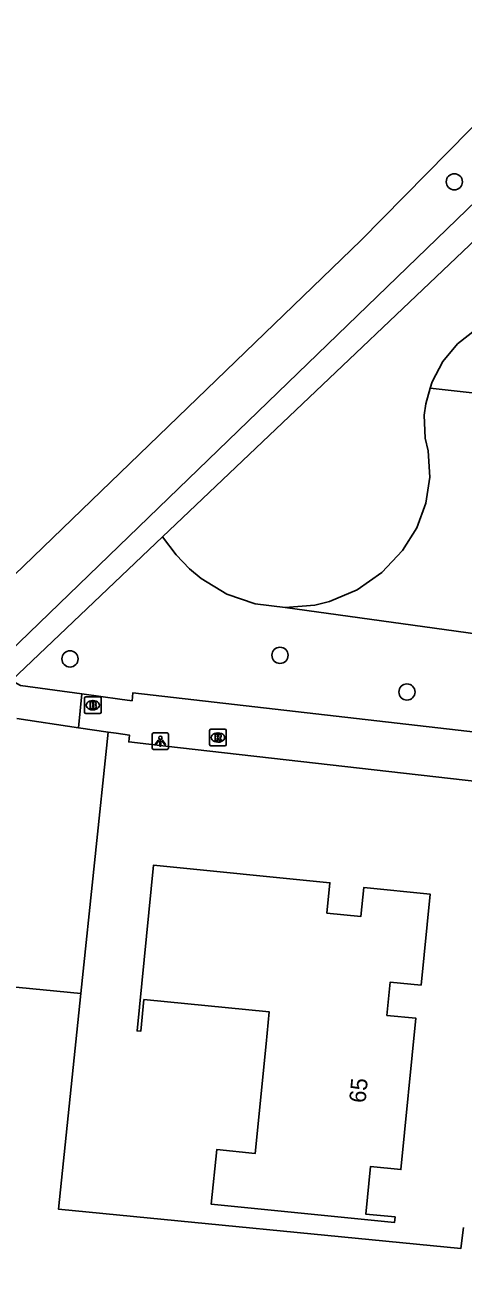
# Model space of a CAD drawing. Extents: x 162398 to 163643, y 386453 to 387397.
# Drawn here: x 162925.6 to 162952, y 387103.2 to 387178.6 of the extents above; entities that cross this region are included whole.
import ezdxf

# ---------------------------------------------------------------- set-up
doc = ezdxf.new("R2010")
doc.units = 0
for name, color, linetype in [('IMGEO_Boom', 7, 'Continuous'), ('IMGEO_Brandkraan', 7, 'Continuous'), ('IMGEO_Groenvoorziening', 7, 'Continuous'), ('IMGEO_Lichtpunt', 7, 'Continuous'), ('IMGEO_Meer_plas_ven_vijver', 7, 'Continuous'), ('IMGEO_Pand', 7, 'Continuous'), ('IMGEO_Pand_nummerreeks', 7, 'Continuous'), ('IMGEO_Rioolput', 7, 'Continuous'), ('IMGEO_Voetpad_halfverhard', 7, 'Continuous'), ('IMGEO_Voetpad_open', 7, 'Continuous')]:
    doc.layers.add(name, color=color, linetype=linetype)

msp = doc.modelspace()

# ---------------------------------------------------------------- linework, layer by layer
at = {"layer": 'IMGEO_Boom'}
for centre in [(162951.492, 387169.124), (162928.28, 387140.296), (162940.961, 387140.515), (162948.63, 387138.296)]:
    msp.add_circle(centre, 0.489, dxfattribs=at)
at = {"layer": 'IMGEO_Brandkraan'}
for p, q in [((162929.155, 387137.072), (162929.155, 387137.924)), ((162929.23, 387137.998), (162930.082, 387137.998)), ((162929.643, 387137.778), (162929.668, 387137.778)), ((162930.156, 387137.924), (162930.156, 387137.072)), ((162930.082, 387136.998), (162929.23, 387136.998)), ((162929.666, 387137.218), (162929.641, 387137.218))]:
    msp.add_line(p, q, dxfattribs=at)
for points in [[(162929.155, 387137.072), (162929.155, 387137.924)], [(162929.23, 387137.998), (162930.082, 387137.998)], [(162929.503, 387137.698), (162929.503, 387137.298), (162929.716, 387137.298)], [(162929.734, 387137.698), (162929.503, 387137.698)], [(162929.682, 387137.617), (162929.628, 387137.617), (162929.628, 387137.541)], [(162929.628, 387137.541), (162929.681, 387137.541)], [(162929.69, 387137.465), (162929.628, 387137.465), (162929.628, 387137.384)], [(162929.628, 387137.384), (162929.69, 387137.384)], [(162930.156, 387137.924), (162930.156, 387137.072)], [(162930.082, 387136.998), (162929.23, 387136.998)]]:
    msp.add_lwpolyline(points, dxfattribs=at)
for centre, radius, start, end in [((162929.232, 387137.922), 0.0765, 91.55205, 178.44795), ((162929.232, 387137.922), 0.0765, 91.55205, 178.44795), ((162929.683, 387137.579), 0.0379, 267.82845, 90.93552), ((162929.691, 387137.424), 0.0404, 269.87594, 90.50774), ((162929.738, 387137.553), 0.145, 59.4692, 91.53667), ((162929.763, 387137.6), 0.0922, 285.51372, 58.15012), ((162929.768, 387137.408), 0.105, 301.31148, 78.98903), ((162930.08, 387137.922), 0.0765, 1.55205, 88.44795), ((162930.08, 387137.922), 0.0765, 1.55205, 88.44795), ((162929.232, 387137.074), 0.0765, 181.55205, 268.44795), ((162929.232, 387137.074), 0.0765, 181.55205, 268.44795), ((162929.722, 387137.549), 0.251, 268.66757, 293.53466), ((162930.08, 387137.074), 0.0765, 271.55205, 358.44795), ((162930.08, 387137.074), 0.0765, 271.55205, 358.44795)]:
    msp.add_arc(centre, radius, start, end, dxfattribs=at)
for centre, major_axis, ratio, start_param, end_param in [((162929.642, 387137.498), (-0.387, 0.002), 0.722429, 4.712389, 7.853982), ((162929.667, 387137.498), (-0.39, 0.002), 0.717154, 1.570796, 4.712389)]:
    msp.add_ellipse(centre, major_axis=major_axis, ratio=ratio, start_param=start_param, end_param=end_param, dxfattribs=at)
at = {"layer": 'IMGEO_Groenvoorziening'}
for points in [[(162950.035, 387156.654), (162950.146, 387157.044), (162950.798, 387158.272), (162951.69, 387159.338), (162952.785, 387160.195), (162954.034, 387160.805), (162955.383, 387161.143), (162956.772, 387161.193), (162971.313, 387159.479), (162974.954, 387164.968), (162979.098, 387161.653), (162978.659, 387160.475)], [(162950.035, 387156.654), (162949.764, 387155.707), (162949.68, 387155.016), (162949.728, 387153.642), (162949.903, 387152.865), (162950.005, 387151.279), (162949.775, 387149.705), (162949.223, 387148.214), (162948.352, 387146.844), (162947.113, 387145.518), (162945.626, 387144.478), (162943.955, 387143.771), (162943.074, 387143.552), (162941.266, 387143.395)], [(162956.38, 387155.957), (162950.035, 387156.654)], [(162941.266, 387143.395), (162939.465, 387143.617), (162937.75, 387144.21), (162936.195, 387145.145), (162935.5, 387145.73), (162934.7, 387146.585), (162933.874, 387147.675)], [(162941.266, 387143.395), (162954.796, 387141.535)], [(162930.576, 387135.875), (162928.93, 387120.073)], [(162924.374, 387120.523), (162928.93, 387120.073)], [(162928.93, 387120.073), (162927.574, 387107.059), (162951.889, 387104.679), (162952.055, 387105.95)]]:
    msp.add_lwpolyline(points, dxfattribs=at)
at = {"layer": 'IMGEO_Lichtpunt'}
for p, q in [((162933.238, 387135.73), (162933.238, 387134.923)), ((162933.238, 387135.73), (162933.238, 387134.923)), ((162934.14, 387135.825), (162933.332, 387135.825)), ((162934.14, 387135.825), (162933.332, 387135.825)), ((162934.234, 387134.923), (162934.234, 387135.73)), ((162934.234, 387134.923), (162934.234, 387135.73)), ((162933.332, 387134.829), (162934.14, 387134.829)), ((162933.332, 387134.829), (162934.14, 387134.829))]:
    msp.add_line(p, q, dxfattribs=at)
for points in [[(162933.612, 387135.394), (162933.651, 387135.366), (162933.463, 387135.104), (162933.425, 387135.131), (162933.612, 387135.394)], [(162933.714, 387135.346), (162933.761, 387135.346), (162933.761, 387135.024), (162933.714, 387135.024), (162933.714, 387135.346)], [(162933.824, 387135.366), (162933.862, 387135.393), (162934.049, 387135.131), (162934.01, 387135.103), (162933.824, 387135.366)]]:
    msp.add_lwpolyline(points, dxfattribs=at)
msp.add_circle((162933.737, 387135.528), 0.0994, dxfattribs=at)
for centre, start, end in [((162933.332, 387135.73), 90, 180), ((162933.332, 387135.73), 90, 180), ((162934.14, 387135.73), 0, 90), ((162934.14, 387135.73), 0, 90), ((162933.332, 387134.923), 180, 270), ((162933.332, 387134.923), 180, 270), ((162934.14, 387134.923), 270, 0), ((162934.14, 387134.923), 270, 360)]:
    msp.add_arc(centre, 0.0946, start, end, dxfattribs=at)
at = {"layer": 'IMGEO_Meer_plas_ven_vijver'}
msp.add_lwpolyline([(162846.89, 387045.895), (162849.85, 387050.53), (162865.986, 387076.424), (162874.5, 387090.087), (162877.58, 387095.446), (162881.241, 387100.793), (162883.801, 387104.202), (162884.941, 387105.402), (162887.051, 387108.121), (162890.58, 387112.23), (162945.852, 387165.587), (162955.059, 387174.946), (162962.124, 387182.486), (162969.073, 387188.983), (162970.442, 387190.315)], dxfattribs=at)
at = {"layer": 'IMGEO_Pand'}
msp.add_lwpolyline([(162932.745, 387119.72), (162940.318, 387118.97), (162940.128, 387117.047), (162939.471, 387110.417), (162937.141, 387110.648), (162936.814, 387107.347), (162947.881, 387106.251), (162947.914, 387106.579), (162946.139, 387106.755), (162946.423, 387109.621), (162948.263, 387109.439), (162949.169, 387118.585), (162947.419, 387118.758), (162947.618, 387120.774), (162949.482, 387120.59), (162950.026, 387126.084), (162946.024, 387126.48), (162945.852, 387124.739), (162943.801, 387124.942), (162943.982, 387126.767), (162933.317, 387127.824), (162932.326, 387117.819), (162932.555, 387117.797), (162932.745, 387119.72)], dxfattribs=at)
at = {"layer": 'IMGEO_Rioolput'}
for p, q in [((162936.713, 387135.12), (162936.713, 387135.972)), ((162936.788, 387136.046), (162937.64, 387136.046)), ((162937.714, 387135.972), (162937.714, 387135.12)), ((162937.224, 387135.266), (162937.199, 387135.266)), ((162937.201, 387135.826), (162937.226, 387135.826)), ((162937.64, 387135.046), (162936.788, 387135.046))]:
    msp.add_line(p, q, dxfattribs=at)
for points in [[(162936.713, 387135.12), (162936.713, 387135.972)], [(162936.788, 387136.046), (162937.64, 387136.046)], [(162937.714, 387135.972), (162937.714, 387135.12)], [(162937.302, 387135.744), (162937.05, 387135.746), (162937.05, 387135.346)], [(162937.05, 387135.346), (162937.174, 387135.346), (162937.174, 387135.508), (162937.185, 387135.508)], [(162937.228, 387135.665), (162937.174, 387135.665), (162937.174, 387135.584)], [(162937.174, 387135.584), (162937.226, 387135.584)], [(162937.232, 387135.479), (162937.303, 387135.346), (162937.443, 387135.346), (162937.378, 387135.472)], [(162937.64, 387135.046), (162936.788, 387135.046)]]:
    msp.add_lwpolyline(points, dxfattribs=at)
for centre, radius, start, end in [((162936.79, 387135.97), 0.0765, 91.55205, 178.44795), ((162936.79, 387135.97), 0.0765, 91.55205, 178.44795), ((162937.638, 387135.97), 0.0765, 1.55205, 88.44795), ((162937.638, 387135.97), 0.0765, 1.55205, 88.44795), ((162936.79, 387135.122), 0.0765, 181.55205, 268.44795), ((162936.79, 387135.122), 0.0765, 181.55205, 268.44795), ((162937.184, 387135.455), 0.0533, 26.02933, 88.69889), ((162937.21, 387135.773), 0.19, 274.7715, 282.96867), ((162937.234, 387135.569), 0.0964, 77.00612, 93.18647), ((162937.248, 387135.626), 0.0378, 276.66336, 79.67722), ((162937.301, 387135.634), 0.109, 350.36119, 89.41601), ((162937.299, 387135.634), 0.112, 277.58423, 350.98172), ((162937.283, 387135.419), 0.108, 29.51342, 73.79051), ((162937.638, 387135.122), 0.0765, 271.55205, 358.44795), ((162937.638, 387135.122), 0.0765, 271.55205, 358.44795)]:
    msp.add_arc(centre, radius, start, end, dxfattribs=at)
for centre, major_axis, ratio, start_param, end_param in [((162937.2, 387135.546), (-0.387, 0.002), 0.722429, 4.712389, 7.853982), ((162937.225, 387135.546), (-0.39, 0.002), 0.717154, 1.570796, 4.712389)]:
    msp.add_ellipse(centre, major_axis=major_axis, ratio=ratio, start_param=start_param, end_param=end_param, dxfattribs=at)
at = {"layer": 'IMGEO_Voetpad_halfverhard'}
for points in [[(162990.622, 387191.429), (162988.981, 387190.548), (162986.564, 387190.198), (162981.995, 387189.888), (162978.312, 387189.488), (162977.07, 387188.884), (162972.048, 387185.44), (162966.778, 387181.153), (162958.243, 387173.224), (162916.196, 387132.579), (162904.234, 387119.646), (162889.742, 387105.631), (162883.217, 387098.659), (162878.712, 387092.096), (162876.773, 387088.486), (162875.505, 387085.945), (162852.417, 387048.899), (162851.569, 387047.532), (162851.368, 387046.853), (162851.155, 387042.928)], [(162991.45, 387188.438), (162989.743, 387188.941), (162980.431, 387188.074), (162977.398, 387187.341), (162973.446, 387184.5), (162967.441, 387179.498), (162959.252, 387171.801), (162933.874, 387147.675)], [(162933.874, 387147.675), (162924.751, 387138.998), (162925.28, 387138.681)]]:
    msp.add_lwpolyline(points, dxfattribs=at)
at = {"layer": 'IMGEO_Voetpad_open'}
for points in [[(162925.28, 387138.681), (162928.991, 387138.18)], [(162928.991, 387138.18), (162928.798, 387136.138)], [(162928.991, 387138.18), (162931.284, 387137.871), (162932.025, 387137.771), (162932.076, 387138.251), (162954.173, 387135.713)], [(162928.798, 387136.138), (162925.06, 387136.69)], [(162928.798, 387136.138), (162930.576, 387135.875)], [(162930.576, 387135.875), (162931.077, 387135.801), (162931.881, 387135.682), (162931.83, 387135.282), (162934.076, 387135.027), (162954.814, 387132.669), (162954.081, 387125.567)]]:
    msp.add_lwpolyline(points, dxfattribs=at)

# ---------------------------------------------------------------- texts
at = {"layer": 'IMGEO_Pand_nummerreeks'}
msp.add_text('65', height=1, rotation=84.34275, dxfattribs=at).set_placement((162946.126, 387113.438))

doc.saveas('drawing.dxf')
